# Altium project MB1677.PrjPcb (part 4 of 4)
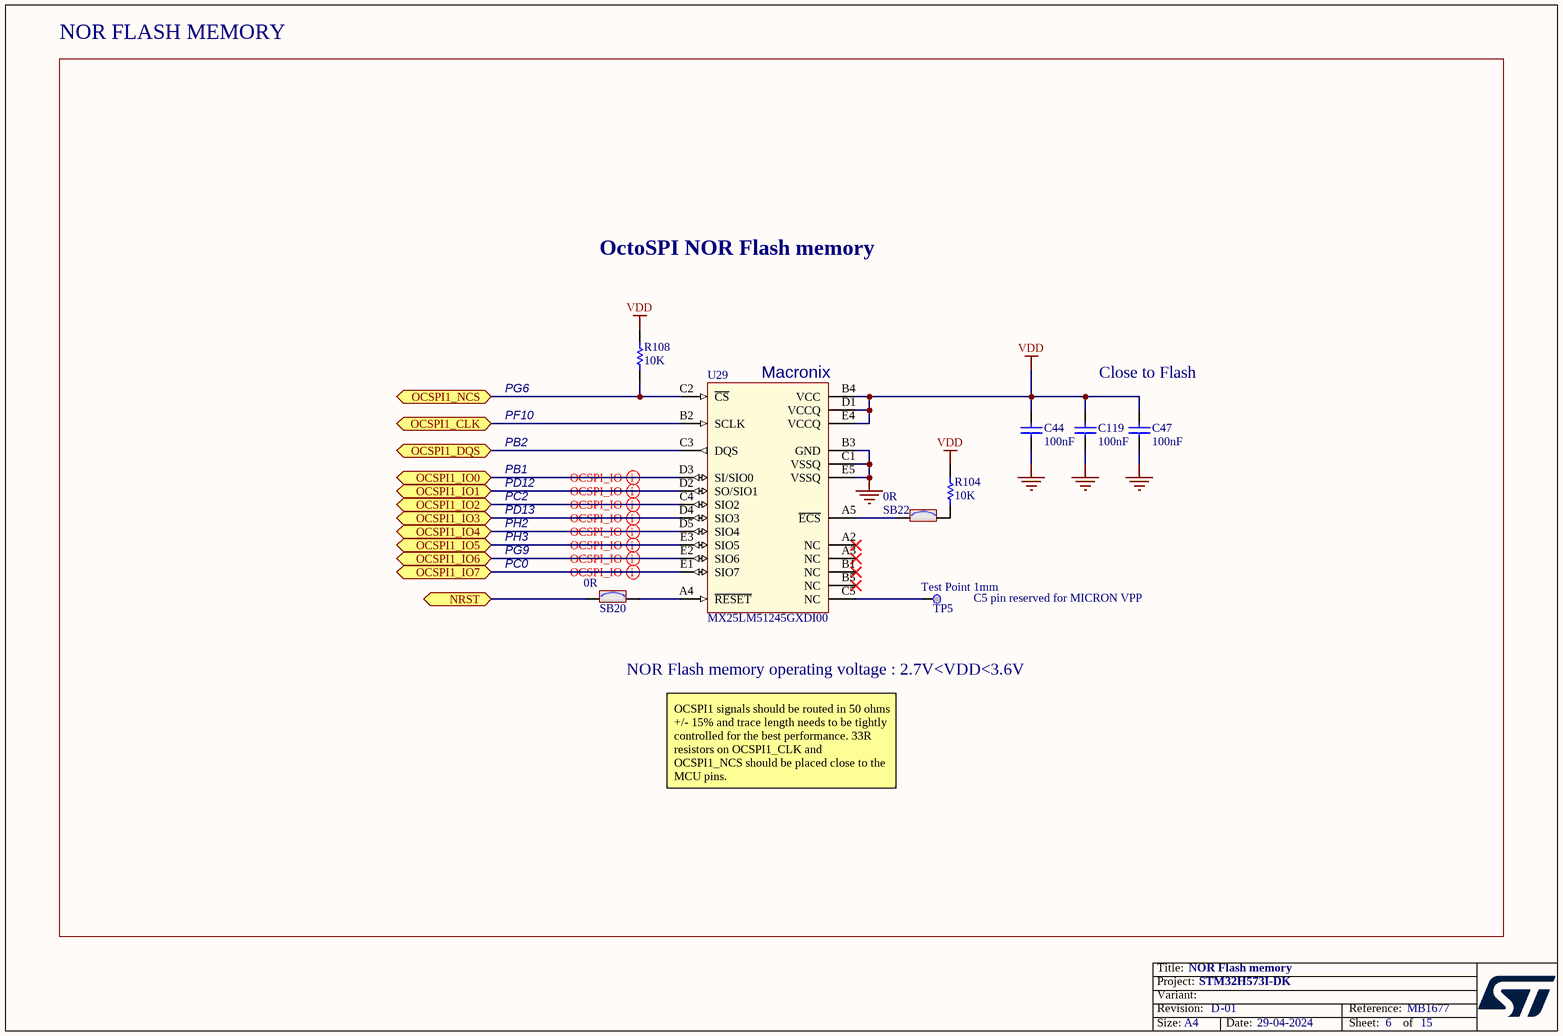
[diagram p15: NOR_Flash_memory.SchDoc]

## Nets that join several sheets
1V8: Audio_Codec (L6.1 L7.1 L8.1), Board_power (JP2.3 SB10.2 TP2.1)
3V3: Audio_Codec (6 pins), LCD (Q3.2 R99.1), Peripherals (6 pins), Arduino (CN14.5 R27.2), Ethernet (L1.2), Board_power (6 pins), STM32_microcontroller_power (SB14.1), STM32_microcontroller_IOs (C107.2 R93.1 X3.4), USB-PD (R56.2)
5V: LCD (R49.1 R103.1), Peripherals (CN3.6 CN3.15), Arduino (CN14.4), STLINK_V3EC (R64.2), Board_power (8 pins), USB-PD (SB28.1)
5V_STLK: STLINK_V3EC (6 pins), Board_power (JP4.1)
5V_UCPD: STLINK_V3EC (D4.1), Board_power (JP4.3), USB-PD (SB29.1)
5V_VIN: Arduino (R90.2), STLINK_V3EC (D3.1), Board_power (5 pins)
GND: Audio_Codec (35 pins), LCD (24 pins), Peripherals (7 pins), Arduino (6 pins), JTAG (13 pins), Ethernet (19 pins), STLINK_V3EC (121 pins), Board_power (15 pins), STM32_microcontroller_power (64 pins), STM32_microcontroller_IOs (9 pins), USB-PD (21 pins), microSDcard (10 pins), NOR_Flash_memory (6 pins)
VBUS_STLK: STLINK_V3EC (12 pins), Board_power (JP4.7)
VDD: Audio_Codec (6 pins), LCD (Q2.2 R100.1), Peripherals (B1.1 B1.2), Arduino (CN14.7), JTAG (CN1.1 CN18.1), Ethernet (7 pins), STLINK_V3EC (9 pins), Board_power (JP2.2), STM32_microcontroller_power (JP6.1), STM32_microcontroller_IOs (SW1.2), USB-PD (U30.2), microSDcard (8 pins), NOR_Flash_memory (8 pins)
VIN: Arduino (CN14.1), Board_power (C32.2 JP3.1 U8.3)
VREFP: Arduino (C110.1 R95.2), STM32_microcontroller_power (C35.2 C36.2 R21.2 U28.N1)
ARD_A0: Arduino (CN16.6), STM32_microcontroller_IOs (U28.R5)
ARD_A1: Arduino (CN16.5), STM32_microcontroller_IOs (U28.M5)
ARD_A2: Arduino (CN16.4), STM32_microcontroller_IOs (U28.P2)
ARD_A3: Arduino (CN16.3), STM32_microcontroller_IOs (U28.R3)
ARD_A4: Arduino (SB24.1), STM32_microcontroller_IOs (U28.P5)
ARD_A5: Arduino (SB23.1), STM32_microcontroller_IOs (U28.N7)
ARD_D0: Arduino (CN15.1), STM32_microcontroller_IOs (U28.N12)
ARD_D1: Arduino (CN15.2), STM32_microcontroller_IOs (U28.M10)
ARD_D2: Arduino (CN15.3), STM32_microcontroller_IOs (U28.A7)
ARD_D3: Arduino (CN15.4), STM32_microcontroller_IOs (U28.A6)
ARD_D4: Arduino (CN15.5), STM32_microcontroller_IOs (U28.J15)
ARD_D5: Arduino (CN15.6), STM32_microcontroller_IOs (U28.P15)
ARD_D6: Arduino (CN15.7), STM32_microcontroller_IOs (U28.N14)
ARD_D7: Arduino (CN15.8), STM32_microcontroller_IOs (U28.H15)
ARD_D8: Arduino (CN13.1), STM32_microcontroller_IOs (U28.G15)
ARD_D9: Arduino (CN13.2), STM32_microcontroller_IOs (U28.F15)
ARD_D10: Arduino (CN13.3), STM32_microcontroller_IOs (U28.N5)
ARD_D11: Arduino (CN13.4), STM32_microcontroller_IOs (U28.M14)
ARD_D12: Arduino (CN13.5), STM32_microcontroller_IOs (U28.B14)
ARD_D13: Arduino (CN13.6 SB15.1), STM32_microcontroller_IOs (U28.A15)
Audio_INT: Audio_Codec (R57.1), STM32_microcontroller_IOs (U28.F3)
DETECTn: Audio_Codec (CN2.10 R70.2 U23.3 U23.10), STM32_microcontroller_IOs (U28.C5)
I2C4_SCL: Audio_Codec (R62.2 R80.1), LCD (CN4.5), STM32_microcontroller_IOs (U28.B5), USB-PD (U30.18)
I2C4_SDA: Audio_Codec (R73.2 R81.1), LCD (CN4.4), STM32_microcontroller_IOs (U28.A4), USB-PD (U30.17)
IBUS_SENSE: STM32_microcontroller_IOs (U28.P7), USB-PD (U30.4)
JTCK: JTAG (R8.2), STLINK_V3EC (CN12.6 R69.2 U3.4 U27.11), STM32_microcontroller_IOs (U28.B13)
JTDI: JTAG (R7.2), STLINK_V3EC (CN12.10 R78.2 U3.1), STM32_microcontroller_IOs (U28.C13)
JTDO: JTAG (R9.2), STLINK_V3EC (CN12.8 R2.1 U3.3 U27.13), STM32_microcontroller_IOs (U28.B7)
JTMS: JTAG (R6.2), STLINK_V3EC (CN12.4 R72.2 U3.5), STM32_microcontroller_IOs (U28.E13)
LCD_A0_RS: LCD (CN7.21), STM32_microcontroller_IOs (U28.F2)
LCD_BL_CTRL: LCD (R55.2 U15.7), STM32_microcontroller_IOs (U28.A14)
LCD_CTP_INT: LCD (CN4.2), STM32_microcontroller_IOs (U28.H13)
LCD_CTP_RST: LCD (CN4.7), STM32_microcontroller_IOs (U28.H14)
LCD_D0: LCD (CN7.18), STM32_microcontroller_IOs (U28.K13)
LCD_D1: LCD (CN7.17), STM32_microcontroller_IOs (U28.J13)
LCD_D2: LCD (CN7.16), STM32_microcontroller_IOs (U28.B12)
LCD_D3: LCD (CN7.15), STM32_microcontroller_IOs (U28.A13)
LCD_D4: LCD (CN7.14), STM32_microcontroller_IOs (U28.R9)
LCD_D5: LCD (CN7.13), STM32_microcontroller_IOs (U28.P9)
LCD_D6: LCD (CN7.12), STM32_microcontroller_IOs (U28.N9)
LCD_D7: LCD (CN7.11), STM32_microcontroller_IOs (U28.R10)
LCD_D8: LCD (CN7.10), STM32_microcontroller_IOs (U28.P10)
LCD_D9: LCD (CN7.9), STM32_microcontroller_IOs (U28.R11)
LCD_D10: LCD (CN7.8), STM32_microcontroller_IOs (U28.P11)
LCD_D11: LCD (CN7.7), STM32_microcontroller_IOs (U28.N10)
LCD_D12: LCD (CN7.6), STM32_microcontroller_IOs (U28.N11)
LCD_D13: LCD (CN7.5), STM32_microcontroller_IOs (U28.M15)
LCD_D14: LCD (CN7.4), STM32_microcontroller_IOs (U28.L13)
LCD_D15: LCD (CN7.3), STM32_microcontroller_IOs (U28.K12)
LCD_NE1_CS: LCD (CN7.22 R44.1), STM32_microcontroller_IOs (U28.G13)
LCD_NOE: LCD (CN7.19), STM32_microcontroller_IOs (U28.B11)
LCD_NWE: LCD (CN7.20), STM32_microcontroller_IOs (U28.A11)
LCD_PWR_ON: LCD (R101.1 R102.1 R103.2), STM32_microcontroller_IOs (U28.G14)
LCD_RST: LCD (CN7.23 R41.2), STM32_microcontroller_IOs (U28.B15)
LCD_TE: LCD (CN7.2), STM32_microcontroller_IOs (U28.A12)
MEMS_LED: Audio_Codec (CN2.12), STM32_microcontroller_IOs (U28.B4)
NJTRST: JTAG (R5.2), STM32_microcontroller_IOs (U28.C7)
NRST: Arduino (CN14.6), JTAG (R4.2), Ethernet (U11.15), STLINK_V3EC (CN12.12 R68.2 U4.5), STM32_microcontroller_IOs (5 pins), NOR_Flash_memory (SB20.1)
OCS_25M: Ethernet (R38.2), STM32_microcontroller_IOs (R94.1)
OCSPI1_CLK: STM32_microcontroller_IOs (R105.1), NOR_Flash_memory (U29.B2)
OCSPI1_DQS: STM32_microcontroller_IOs (R107.1), NOR_Flash_memory (U29.C3)
OCSPI1_IO0: STM32_microcontroller_IOs (R118.1), NOR_Flash_memory (U29.D3)
OCSPI1_IO1: STM32_microcontroller_IOs (R119.2), NOR_Flash_memory (U29.D2)
OCSPI1_IO2: STM32_microcontroller_IOs (R109.2), NOR_Flash_memory (U29.C4)
OCSPI1_IO3: STM32_microcontroller_IOs (R115.2), NOR_Flash_memory (U29.D4)
OCSPI1_IO4: STM32_microcontroller_IOs (R114.2), NOR_Flash_memory (U29.D5)
OCSPI1_IO5: STM32_microcontroller_IOs (R120.2), NOR_Flash_memory (U29.E3)
OCSPI1_IO6: STM32_microcontroller_IOs (R117.2), NOR_Flash_memory (U29.E2)
OCSPI1_IO7: STM32_microcontroller_IOs (R116.2), NOR_Flash_memory (U29.E1)
OCSPI1_NCS: STM32_microcontroller_IOs (R106.2), NOR_Flash_memory (R108.2 U29.C2)
PDM_SAI1_CK1: Audio_Codec (U23.16), STM32_microcontroller_IOs (U28.L14)
PDM_SAI1_SD1: Audio_Codec (U23.5), STM32_microcontroller_IOs (U28.B10)
PDM_SAI1_SD2: Audio_Codec (CN2.5), STM32_microcontroller_IOs (U28.C3)
PDM_SAI1_SD3: Audio_Codec (CN2.7), STM32_microcontroller_IOs (U28.N3)
PMOD11: Peripherals (CN3.11 CN6.7), STM32_microcontroller_IOs (U28.M12)
PMOD12: Peripherals (CN3.12 CN6.8), STM32_microcontroller_IOs (U28.P13)
RMII_CRS_DV: Ethernet (R28.1), STM32_microcontroller_IOs (U28.R4)
RMII_MDC: Ethernet (U11.13), STM32_microcontroller_IOs (U28.L2)
RMII_MDIO: Ethernet (R34.1 U11.12), STM32_microcontroller_IOs (U28.M3)
RMII_REF_CLK: Ethernet (R37.1), STM32_microcontroller_IOs (U28.L3)
RMII_RX_ER: Ethernet (R29.1 U11.10), STM32_microcontroller_IOs (U28.F4)
RMII_RXD0: Ethernet (R31.1), STM32_microcontroller_IOs (U28.N4)
RMII_RXD1: Ethernet (R33.1), STM32_microcontroller_IOs (U28.P4)
RMII_TX_EN: Ethernet (U11.16), STM32_microcontroller_IOs (U28.C9)
RMII_TXD0: Ethernet (U11.17), STM32_microcontroller_IOs (U28.C8)
RMII_TXD1: Ethernet (U11.18), STM32_microcontroller_IOs (U28.B8)
SAI2_FS_A: Audio_Codec (U25.30), STM32_microcontroller_IOs (U28.A1)
SAI2_MCLK_A: Audio_Codec (U25.28), STM32_microcontroller_IOs (U28.B3)
SAI2_SCK_A: Audio_Codec (U25.29), STM32_microcontroller_IOs (U28.A2)
SAI2_SD_A: Audio_Codec (U25.32), STM32_microcontroller_IOs (U28.C4)
SAI2_SD_B: Audio_Codec (U25.31), STM32_microcontroller_IOs (U28.A9)
SDIO1_CK: STM32_microcontroller_IOs (U28.C11), microSDcard (CN5.5 U5.2 U5.9)
SDIO1_CMD: STM32_microcontroller_IOs (U28.C10), microSDcard (CN5.3 R13.1 U5.1 U5.10)
SDIO1_D0: STM32_microcontroller_IOs (U28.F14), microSDcard (CN5.7 R12.1 U5.4 U5.7)
SDIO1_D1: STM32_microcontroller_IOs (U28.F13), microSDcard (CN5.8 R11.1 U5.5 U5.6)
SDIO1_D2: STM32_microcontroller_IOs (U28.D12), microSDcard (CN5.1 R18.1 U7.1 U7.10)
SDIO1_D3: STM32_microcontroller_IOs (U28.C12), microSDcard (CN5.2 R16.1 U7.2 U7.9)
STMOD#1: Peripherals (SB5.1 SB9.1), STM32_microcontroller_IOs (U28.H1)
STMOD#2: Peripherals (SB7.1 SB8.1), STM32_microcontroller_IOs (U28.J3)
STMOD#3: Peripherals (SB3.1 SB6.1), STM32_microcontroller_IOs (U28.K2)
STMOD#4: Peripherals (SB2.1 SB4.1), STM32_microcontroller_IOs (U28.H2)
STMOD#8-MOSIs: Peripherals (CN3.8), STM32_microcontroller_IOs (U28.N13)
STMOD#9-MISOs: Peripherals (CN3.9), STM32_microcontroller_IOs (U28.P14)
STMOD#13-ADC: Peripherals (CN3.13), STM32_microcontroller_IOs (U28.R6)
STMOD#14-PWM: Peripherals (CN3.14), STM32_microcontroller_IOs (U28.M13)
STMOD#17: Peripherals (CN3.17), STM32_microcontroller_IOs (U28.G2)
STMOD#18: Peripherals (CN3.18), STM32_microcontroller_IOs (U28.L12)
STMOD#19: Peripherals (CN3.19), STM32_microcontroller_IOs (U28.R1)
STMOD#20: Peripherals (CN3.20), STM32_microcontroller_IOs (U28.P1)
TRACECLK: JTAG (CN18.12 U17.1), STM32_microcontroller_IOs (U28.D4)
TRACED0: JTAG (CN18.14 R97.1 U16.4), STM32_microcontroller_IOs (U28.B2)
TRACED1: JTAG (CN18.16 R98.1 U16.3), STM32_microcontroller_IOs (U28.A8)
TRACED2: JTAG (CN18.18 U16.1), STM32_microcontroller_IOs (U28.D3)
TRACED3: JTAG (CN18.20 U16.5), STM32_microcontroller_IOs (U28.C2)
UCPD_CC1: STM32_microcontroller_IOs (U28.R15), USB-PD (U30.1)
UCPD_CC2: STM32_microcontroller_IOs (U28.N15), USB-PD (U30.3)
UCPD_FLT: STM32_microcontroller_IOs (U28.P8), USB-PD (U30.19)
UCPD_PWR: STM32_microcontroller_IOs (U28.R8), USB-PD (U30.20)
USB_FS_N: STM32_microcontroller_IOs (U28.D15), USB-PD (CN17.A7 CN17.B7 U31.1 U31.6)
USB_FS_P: STM32_microcontroller_IOs (U28.C15), USB-PD (CN17.A6 CN17.B6 U31.3 U31.4)
uSD_Detect: STM32_microcontroller_IOs (U28.D13), microSDcard (CN5.9 R10.1)
USER_LED1: Peripherals (R26.1), STM32_microcontroller_IOs (U28.E1)
USER_LED2: Peripherals (R25.1), STM32_microcontroller_IOs (U28.E2)
USER_LED3: Peripherals (R24.1), STM32_microcontroller_IOs (U28.F1)
USER_LED4: Peripherals (R22.1), STM32_microcontroller_IOs (U28.G1)
VBUS_SENSE: STM32_microcontroller_IOs (U28.R7), USB-PD (C122.2 R124.2 R125.1)
WAKEUP: Peripherals (5 pins), STM32_microcontroller_IOs (U28.E3)

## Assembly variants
H573I: not fitted C26 C34 C60 C61 C96 C115 C125 CN1 CN11 D3 D4 R10 R44 R95 R99 R100 R138 R139 SB2 SB5 SB6 SB8 SB18 SB21 SB22 SB25 U21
